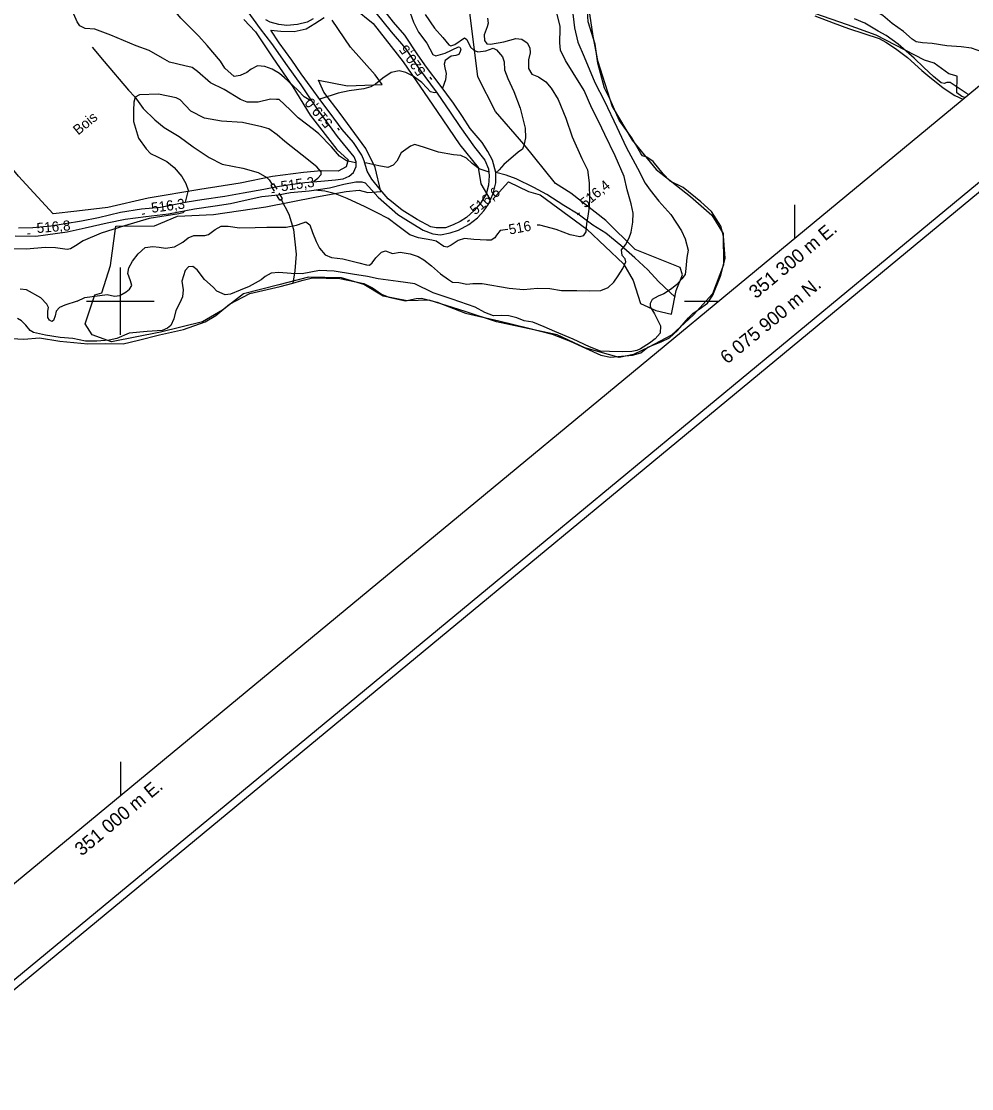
# Model space of a CAD drawing. Extents: x 347059 to 352153, y 6073752 to 6078601.
# Drawn here: x 350955.9 to 351378.9, y 6075549.6 to 6076024.5 of the extents above; entities that cross this region are included whole.
import ezdxf

# ---------------------------------------------------------------- set-up
doc = ezdxf.new("R2010")
doc.units = 0
for name, color, linetype in [('Level 1', 7, 'Continuous'), ('Level 2', 7, 'Continuous'), ('Level 21', 7, 'Continuous'), ('Level 22', 7, 'Continuous'), ('Level 26', 7, 'Continuous'), ('Level 3', 7, 'Continuous'), ('Level 4', 7, 'Continuous'), ('Level 44', 7, 'Continuous'), ('Level 60', 7, 'Continuous'), ('Level 61', 7, 'Continuous')]:
    doc.layers.add(name, color=color, linetype=linetype)

msp = doc.modelspace()

# ---------------------------------------------------------------- linework, layer by layer
at = {"layer": 'Level 1'}
for points in [[(351067.54, 6076003.28), (351064.33, 6076004.41), (351061, 6076004.75), (351058.26, 6076003.32), (351056.28, 6076001.76), (351053.33, 6076000.43), (351050.66, 6076000), (351046.49, 6076003.64), (351044.51, 6076006.88), (351038.58, 6076013.82), (351034.94, 6076017.92), (351026.87, 6076025.96), (351023.59, 6076029.96), (351021.08, 6076033.82), (351018.95, 6076038.01), (351015.73, 6076043.8), (351011.84, 6076051.29), (351006.56, 6076061.33)], [(351128.99, 6076028.34), (351130.47, 6076024.14), (351132.72, 6076019.66), (351136.44, 6076014.85), (351139.14, 6076009.83), (351140.38, 6076009.16), (351144.53, 6076010.32), (351150.45, 6076013.25), (351151.06, 6076013.01), (351151.5, 6076012.18), (351151.28, 6076011.06), (351150.62, 6076009.82), (351149.37, 6076009.28), (351147.21, 6076009.03), (351144.58, 6076007.17), (351144.1, 6076005.41), (351144.35, 6076003.89), (351144.95, 6076001.34), (351144.68, 6075998.57)], [(351085.36, 6075988.98), (351083.98, 6075989.61), (351081.87, 6075991.01), (351079, 6075993.89), (351074.52, 6075998.05), (351073.05, 6075999.47), (351070.82, 6076001.3), (351067.54, 6076003.28)], [(351140.77, 6075992.82), (351139.78, 6075992.74), (351138.03, 6075993.24), (351136.37, 6075994.88), (351134.18, 6075997.27), (351130.32, 6076000.1), (351127.09, 6076001.72), (351124.07, 6076002.47), (351120.53, 6076001.83), (351116.85, 6075999.19), (351113.59, 6075996.52), (351111.44, 6075995.33), (351108.39, 6075994.58), (351101.9, 6075993.67), (351096.9, 6075992.58), (351089.23, 6075989.99), (351088.78, 6075989.8)], [(351144.68, 6075998.57), (351143.45, 6075994.86), (351143.3, 6075994.74)]]:
    msp.add_lwpolyline(points, dxfattribs=at)
at = {"layer": 'Level 2'}
for points in [[(351394.98, 6076006.41), (351394.56, 6076006.7), (351390.72, 6076008.51), (351386.33, 6076009.86), (351378.78, 6076012.53), (351374.27, 6076013.23), (351367.78, 6076013.57), (351361.34, 6076014.63), (351356.95, 6076015.03), (351354.16, 6076015.46), (351352.36, 6076016.61), (351348.57, 6076020.09), (351343.46, 6076023.52), (351339.31, 6076027.1), (351335.85, 6076029.25), (351330.86, 6076030.35), (351328.52, 6076032.12), (351326.69, 6076033.78), (351321.7, 6076038.81), (351319, 6076040.54), (351315.61, 6076041.66), (351309.69, 6076044)], [(351061.31, 6075988.58), (351056.44, 6075988.55), (351053.45, 6075989.72), (351046.26, 6075994.26), (351040.17, 6075997.2), (351034.38, 6076002.27), (351032, 6076003.97), (351028.75, 6076004.67), (351021.93, 6076006.44), (351018.76, 6076008.14), (351012.78, 6076011.57), (351007.05, 6076013.62), (350995.79, 6076018.42), (350988.6, 6076021.09), (350984.39, 6076021.36), (350981.9, 6076022.57), (350980.74, 6076024.39), (350979.26, 6076027.68)], [(351201.14, 6076030.4), (351202.11, 6076021.65), (351203.59, 6076015.27), (351206.5, 6076008.77), (351211.12, 6075997.31), (351215.55, 6075989.03), (351220.95, 6075977.43), (351225.12, 6075968.52), (351230.18, 6075959.18), (351233.58, 6075952.57), (351235.79, 6075949.37), (351239.74, 6075944.58), (351245.04, 6075938.54), (351249.75, 6075931.31), (351251.36, 6075927.73), (351252.73, 6075922.72), (351252.14, 6075919.52), (351251.72, 6075914.59), (351251.32, 6075911.95), (351249.97, 6075909.97), (351247.72, 6075907.49), (351245.28, 6075905.53), (351241.89, 6075903.28), (351239.33, 6075902.26), (351236.65, 6075900.74), (351235.88, 6075899), (351235.85, 6075897.49), (351237.78, 6075894.45), (351240.48, 6075889.12), (351240.25, 6075885.82), (351237.99, 6075883.19), (351235.57, 6075881.37), (351231.52, 6075878.81), (351229.82, 6075878.01), (351227.72, 6075877.67), (351223.34, 6075877.52), (351217.69, 6075877.61), (351213.77, 6075877.85), (351208.88, 6075879.68), (351201.6, 6075883.08), (351193.32, 6075886.55), (351188.66, 6075888.59), (351183.65, 6075890.72), (351179.68, 6075891.33), (351176.54, 6075892.66), (351172.94, 6075893.45), (351169.59, 6075893.65), (351166.13, 6075893.49), (351162.22, 6075894.96), (351157.94, 6075897.32), (351147.72, 6075900.89), (351139.23, 6075903.66), (351131.12, 6075907.7), (351126.86, 6075908.33), (351123.66, 6075908.81), (351114.77, 6075910.03)], [(351135.72, 6076027.57), (351139.79, 6076021.57), (351143.56, 6076017.32), (351146.25, 6076014.02), (351147.14, 6076013.58), (351148.91, 6076014.3), (351153.23, 6076017.23), (351154.27, 6076016.51), (351155.81, 6076013.02), (351157.35, 6076011.67), (351159.09, 6076011.03), (351162.61, 6076011.39), (351165.98, 6076012.54), (351167.43, 6076011.92), (351170.05, 6076008.7), (351170.89, 6076006.48), (351171, 6076002.96), (351172.51, 6075999.18), (351175.16, 6075993.3)], [(351163.35, 6076026.01), (351163.69, 6076023.75), (351163.29, 6076022.07), (351161.9, 6076018.59), (351162.14, 6076015.99), (351163.11, 6076014.54), (351164.81, 6076014.4), (351170.74, 6076015.35), (351175.99, 6076016.93), (351178.68, 6076016.57), (351181.07, 6076015.01), (351182.2, 6076012.76), (351182.39, 6076010.52), (351181.67, 6076007.35)], [(351196.36, 6075904.83), (351203.22, 6075904.71), (351208.86, 6075904.61), (351213.81, 6075904.72), (351217.12, 6075906.11), (351219.58, 6075908.5), (351221.64, 6075911.36), (351223.72, 6075914.5), (351225, 6075917.49), (351224.67, 6075918.81), (351223.41, 6075920.28), (351223.02, 6075922.88), (351224.89, 6075925.11), (351226.47, 6075928.17), (351227.3, 6075930.76), (351228.12, 6075935.23), (351228.18, 6075939.18), (351227.4, 6075943.34), (351225.63, 6075949.59), (351224.26, 6075955.53), (351220.19, 6075964.63), (351215.64, 6075974.13), (351212.98, 6075979.89), (351209.91, 6075985.96), (351206.39, 6075993.79), (351201.51, 6076001.67), (351198.11, 6076007.05), (351195.94, 6076011.75), (351195.59, 6076014.94), (351195.69, 6076021.33), (351195.77, 6076022.31), (351194.34, 6076028.31)], [(351367.81, 6075997.28), (351366.63, 6075996.94), (351365.27, 6075997.25), (351361.99, 6075999.97), (351357.58, 6076004.01), (351353.24, 6076008.12), (351346.16, 6076014.32), (351340.79, 6076018.22), (351337.23, 6076020.16), (351331.33, 6076023.73), (351326.83, 6076025.67)], [(351181.67, 6076007.35), (351181.69, 6076003.62), (351183.14, 6076000.99), (351186.13, 6075999.81), (351189.33, 6075997.61), (351191.7, 6075994.83), (351194.92, 6075989.83), (351198.25, 6075981.45), (351201.09, 6075973.18), (351205.34, 6075963.57), (351207.9, 6075958.41), (351208.7, 6075952.67), (351208.87, 6075944.9), (351208.44, 6075940.91), (351208.04, 6075937.86), (351207.43, 6075934.54), (351207.23, 6075930.88), (351205.96, 6075929.12), (351204.58, 6075928.72), (351200.28, 6075929.57), (351194.02, 6075931.95), (351186.73, 6075933.83), (351185.55, 6075933.82)], [(351377.49, 6075991.96), (351376.39, 6075992.64), (351369.27, 6075997.32), (351367.81, 6075997.28)], [(351175.16, 6075993.3), (351177.99, 6075985.97), (351180.21, 6075977.04), (351180.26, 6075972.67), (351179.59, 6075969.28), (351178.98, 6075967.68), (351177.03, 6075966.4), (351170.65, 6075960.85), (351168.62, 6075958.5), (351167.13, 6075957.18)], [(351085.98, 6075953.1), (351086.19, 6075953.39), (351087.93, 6075954.76), (351089.34, 6075956.37), (351089.42, 6075957.52), (351087.44, 6075959.83), (351080.86, 6075965.04), (351073.2, 6075971.06), (351069.83, 6075974.07), (351066.09, 6075976.74), (351062.93, 6075977.65), (351054.39, 6075979.56), (351044.97, 6075980.19), (351037.39, 6075981.45), (351031.44, 6075984.52), (351026.57, 6075989.6), (351024.85, 6075990.53), (351017, 6075992.1), (351008.51, 6075991.79), (351006.56, 6075990.76), (351006.05, 6075988.6), (351005.85, 6075984.8), (351005.92, 6075979.9), (351008.11, 6075972.52), (351011.43, 6075967.86), (351013.43, 6075965.68), (351016.49, 6075964.28), (351020.64, 6075962.22), (351023.97, 6075959.57), (351027.33, 6075955.49), (351029.19, 6075952.38), (351030.19, 6075949.35), (351028.83, 6075944.02)], [(351104.96, 6075961.63), (351104.08, 6075961.66), (351100.7, 6075962.48), (351097.56, 6075964.6), (351094, 6075968.76), (351088.33, 6075974.46), (351085.97, 6075976.45), (351079.19, 6075981.6), (351075.51, 6075985.13), (351070.62, 6075989.76), (351069.55, 6075989.78), (351066.77, 6075989.93), (351061.31, 6075988.58)], [(351164, 6075957.53), (351163.66, 6075957.61), (351159.66, 6075958.92), (351156.55, 6075961.32), (351154, 6075963.68), (351151.58, 6075964.81), (351148.32, 6075965.07), (351141.56, 6075966.34), (351135.34, 6075968.35), (351131.01, 6075969.71), (351129.11, 6075969), (351124.96, 6075965.96), (351122.99, 6075962.39), (351121.36, 6075960.59), (351118.99, 6075959.48), (351115.12, 6075960.3), (351109.77, 6075961.48), (351108.79, 6075961.51)], [(351123.57, 6075933.54), (351119.15, 6075936.84), (351114.04, 6075939.41), (351109, 6075942.05), (351100.89, 6075945.65), (351095.74, 6075947.8), (351090.95, 6075948.9), (351086.41, 6075949.38), (351086.38, 6075949.48)], [(351028.57, 6075940.24), (351028.56, 6075940.13), (351027.82, 6075939.39), (351026.06, 6075938.95), (351012.77, 6075936.78), (351001.83, 6075933.56), (350991.39, 6075930.22), (350983.46, 6075926.89), (350980, 6075924.72), (350977.88, 6075923.3), (350976.28, 6075923), (350971.09, 6075923.78), (350966.64, 6075923.85), (350958.1, 6075923.09), (350952.14, 6075923.35)], [(350980.85, 6075900.05), (350984.22, 6075901.73), (350994.09, 6075902.96), (350997.42, 6075902.19), (350999.75, 6075902.58), (351002.53, 6075904.16), (351004.13, 6075905.4), (351005.04, 6075906.99), (351004.54, 6075909.12), (351003.27, 6075912.33), (351003.81, 6075914.81), (351005.39, 6075917.79), (351008, 6075921.12), (351011.01, 6075923.84), (351014.42, 6075924.35), (351017.27, 6075923.98), (351020.06, 6075923.68), (351024.12, 6075924.22), (351027.86, 6075926.23), (351030.16, 6075928.21), (351032.75, 6075929.23), (351037.64, 6075929.27), (351039.25, 6075929.72), (351042.14, 6075931.94), (351044.91, 6075933.37), (351047.93, 6075933.42), (351053.05, 6075932.72), (351060.02, 6075932.8), (351065.2, 6075932.96), (351073.82, 6075932.99), (351078.33, 6075933.78), (351081.42, 6075934.83), (351082.56, 6075935.29), (351084.37, 6075934.01), (351085.49, 6075930.53), (351087.14, 6075926.58), (351088.65, 6075923.58), (351091.16, 6075920.63), (351093.94, 6075919.4), (351099, 6075918.92), (351106.12, 6075917.12), (351109.57, 6075916.2), (351110.85, 6075916.1), (351112.06, 6075917.01), (351113.66, 6075919.33), (351116.2, 6075921.79), (351118.04, 6075922.43), (351121.11, 6075921.18), (351124.59, 6075921.76), (351128.99, 6075921.12), (351132.56, 6075919.9), (351135.11, 6075918.47), (351138.43, 6075915.82), (351142.47, 6075912.18), (351146.09, 6075909.66), (351147.79, 6075908.44), (351150.65, 6075908.36), (351154.18, 6075907.64), (351156.92, 6075907.85), (351161, 6075907.88), (351173.02, 6075905.77), (351179.43, 6075905.25), (351185.62, 6075905.76), (351191.13, 6075905.68), (351196.36, 6075904.83)], [(351172.4, 6075931.91), (351168.99, 6075931.52), (351167.4, 6075929.35), (351166.68, 6075928.19), (351165.03, 6075927.17), (351162.95, 6075927.12), (351157.4, 6075927.43), (351153.14, 6075927.91), (351150.36, 6075926.99), (351147.29, 6075925.01), (351145.43, 6075924.08), (351144.02, 6075924.34), (351140.54, 6075926.7), (351138.65, 6075927.21), (351132.71, 6075928.27), (351128.8, 6075929.59), (351123.57, 6075933.54)], [(351114.77, 6075910.03), (351109.96, 6075910.99), (351103.35, 6075912.03), (351095.18, 6075913.33), (351088.67, 6075913.64), (351080.87, 6075912.17), (351075.97, 6075912.28), (351070.49, 6075912.79), (351067.16, 6075912.48), (351064.46, 6075910.96), (351062.7, 6075909.59), (351057.38, 6075906.62), (351053.3, 6075904.85), (351049, 6075903.17), (351046.61, 6075902.86), (351042.98, 6075904.45), (351041.31, 6075906.25), (351037.39, 6075909.74), (351034.23, 6075913.9), (351032.19, 6075915.51), (351030.37, 6075915.29), (351028.82, 6075913.68), (351027.32, 6075908.89), (351027.97, 6075905), (351027.61, 6075901.99), (351026.55, 6075899.33), (351024.72, 6075895.86), (351023.87, 6075892.17), (351022.51, 6075889.24), (351020.98, 6075888.06), (351018.6, 6075886.95), (351012.01, 6075886.54), (351003.88, 6075885.74), (350998.38, 6075883.43), (350995.01, 6075882.69)], [(350980.85, 6075900.05), (350975.32, 6075898.25), (350972.95, 6075897.28), (350971.46, 6075895.6), (350971.01, 6075893.46), (350970.28, 6075891.35), (350969.54, 6075890.98), (350968.42, 6075891.5), (350967.72, 6075892.79), (350967.78, 6075895.53), (350968.05, 6075897.24), (350967.3, 6075898.75), (350964.54, 6075901.5), (350958.18, 6075905.04), (350955.39, 6075905.34)], [(350995.01, 6075882.69), (350989.57, 6075882.18), (350984.45, 6075882.23), (350978.92, 6075883.4), (350973.26, 6075883.92), (350966.69, 6075884.88), (350961.29, 6075886.03), (350959.84, 6075886.94), (350957.92, 6075889.34), (350955.98, 6075891.31), (350954.17, 6075892.32)]]:
    msp.add_lwpolyline(points, dxfattribs=at)
at = {"layer": 'Level 21'}
for points in [[(351123.45, 6075938.63), (351128.32, 6075935.62), (351134.76, 6075931.68), (351139.06, 6075929.98), (351142.52, 6075929.59), (351146.86, 6075930.45), (351150.47, 6075931.59), (351155.09, 6075934.09), (351159, 6075937.12), (351161.74, 6075940.21), (351163.86, 6075943.23), (351165.97, 6075947.88), (351167.05, 6075952.63), (351167.14, 6075957.31), (351165.64, 6075962.83), (351163.62, 6075966.64), (351161.04, 6075970.58), (351155.7, 6075976.9), (351152.35, 6075982.13), (351148.31, 6075988.13), (351142.28, 6075996.1), (351136.21, 6076004.19), (351132.45, 6076009.67), (351126.57, 6076018.44), (351121.6, 6076024.11), (351115.66, 6076031.78)], [(350954.73, 6075932.59), (350961.02, 6075932.83), (350969.1, 6075933.51), (350975.5, 6075934.52), (350982.74, 6075935.77), (350990.24, 6075937.24), (351000.02, 6075939.57), (351009.45, 6075941.07), (351017.86, 6075941.8), (351029.68, 6075944.19), (351036.33, 6075945.25), (351046.48, 6075946.68), (351054.69, 6075948.3), (351063.8, 6075949.83), (351069.9, 6075951.11), (351074.57, 6075951.78), (351082.15, 6075952.8), (351089.28, 6075953.37), (351095.77, 6075953.99), (351099.1, 6075954.46), (351101.89, 6075955.59), (351103.76, 6075957.29), (351104.96, 6075960), (351104.95, 6075962.08), (351104.11, 6075964.27), (351096.66, 6075973.31), (351091.85, 6075979.87), (351087.69, 6075985.47), (351083.15, 6075992.32), (351080.41, 6075996.28), (351074.37, 6076004.78), (351067.41, 6076014.66), (351062.44, 6076021.15), (351056.14, 6076029.88)], [(351085.79, 6076025.7), (351083.09, 6076024.2), (351078.85, 6076023.13), (351074.07, 6076022.72), (351070.54, 6076023.12), (351066.71, 6076024.17), (351064.74, 6076025.21)], [(351113.75, 6076028.34), (351120.52, 6076019.93), (351126.92, 6076012.41), (351132.59, 6076003.99), (351140.97, 6075992.54), (351146.85, 6075984.14), (351151.05, 6075977.76), (351157.63, 6075968.6), (351162.21, 6075962.76), (351163.87, 6075958.94), (351164.17, 6075955.78), (351163.8, 6075951.61), (351162.85, 6075947.63), (351160.31, 6075943.66), (351157.42, 6075940.3), (351154.04, 6075937.27), (351151.31, 6075935.52), (351148.08, 6075933.95), (351144.65, 6075932.59), (351140.56, 6075932.68), (351138.16, 6075933.06), (351132.07, 6075936.39), (351125.44, 6075940.55), (351119.26, 6075945.52), (351115.65, 6075949.72), (351111.99, 6075954.34), (351109.81, 6075957.8), (351108.55, 6075962.4), (351107.54, 6075964.98), (351103.75, 6075970.66), (351098.69, 6075976.34), (351093.39, 6075983.68), (351089.29, 6075989.1), (351084.88, 6075995.09), (351080.44, 6076001.2), (351076.28, 6076007.24), (351070.66, 6076015.05), (351066.98, 6076020.6), (351071.48, 6076020.19), (351077.3, 6076020.06), (351082.68, 6076021.19), (351086.63, 6076023.51), (351090.66, 6076026.19)], [(350953.23, 6075929.14), (350962.36, 6075928.94), (350966.76, 6075929.47), (350976.33, 6075930.88), (350984.4, 6075932.66), (350994.17, 6075934.91), (351002.18, 6075936.58), (351011.4, 6075937.69), (351021.41, 6075938.94), (351033, 6075941.05), (351042.21, 6075942.45), (351049.03, 6075943.5), (351055.52, 6075944.95), (351062.99, 6075946.55), (351070.19, 6075947.31), (351075.74, 6075948.36), (351084.04, 6075949.14), (351093.03, 6075950.44), (351099.52, 6075952.04), (351104.75, 6075953.19), (351107.47, 6075953.15), (351109.01, 6075952.72), (351114.81, 6075946.32), (351123.45, 6075938.63)]]:
    msp.add_lwpolyline(points, dxfattribs=at)
at = {"layer": 'Level 22'}
msp.add_lwpolyline([(351246.87, 6075901.79), (351239.58, 6075908.84), (351234.72, 6075914.02), (351229.06, 6075919.28), (351222.81, 6075924.79), (351216.11, 6075930.22), (351210.34, 6075933.9), (351203.79, 6075938.78), (351197.42, 6075942.54), (351189.83, 6075947.44), (351184.08, 6075950.54), (351176.14, 6075954.4), (351171.69, 6075956.12), (351167.14, 6075957.31)], dxfattribs=at)
at = {"layer": 'Level 26'}
for p, q in [((351068.19, 6075952.27), (351066.95, 6075951.49)), ((351066.95, 6075951.49), (351068.48, 6075949.04)), ((351068.19, 6075952.27), (351069.71, 6075949.81)), ((351070.94, 6075944.91), (351069.49, 6075947.39)), ((351072.2, 6075945.66), (351070.71, 6075948.13)), ((351070.94, 6075944.91), (351072.2, 6075945.66))]:
    msp.add_line(p, q, dxfattribs=at)
at = {"layer": 'Level 3'}
for p, q in [((351138.58, 6075998.72), (351137.89, 6075999.7)), ((351097.57, 6075976.09), (351096.8, 6075977.01)), ((351067.42, 6075948.37), (351068.61, 6075948.53)), ((351009.73, 6075938.81), (351010.92, 6075938.97)), ((351154.53, 6075935.44), (351155.45, 6075936.21)), ((351203.47, 6075938.5), (351204.39, 6075939.27)), ((350958.64, 6075930), (350959.84, 6075930.1))]:
    msp.add_line(p, q, dxfattribs=at)
at = {"layer": 'Level 4'}
for points in [[(351268.38, 6075929.02), (351267.23, 6075933.43), (351263.11, 6075939.98), (351258.39, 6075944.18), (351250.51, 6075950.6), (351244.76, 6075953.42), (351241.66, 6075956.73), (351237.19, 6075962.18), (351234.28, 6075964.17), (351232.46, 6075964.67), (351231.67, 6075965.8), (351227.62, 6075972.73), (351222.07, 6075980.5), (351218.08, 6075989.72), (351215.52, 6075994.83), (351212.56, 6076005.89), (351211.39, 6076014.33), (351208.24, 6076024.26), (351207.59, 6076033.88)], [(351309.11, 6076027.06), (351317.23, 6076023.89), (351324.03, 6076021.33), (351337.77, 6076016.94), (351340.66, 6076015.32), (351345.06, 6076012.41), (351350.32, 6076008.44), (351356.66, 6076002.61), (351359.42, 6076000.43), (351366.2, 6075994.97), (351371.48, 6075991.61), (351374.96, 6075989.87)], [(350987.4, 6076013.03), (350992.75, 6076006.73), (351003.59, 6075993.96), (351006.39, 6075990.92), (351010.21, 6075985.74), (351015.31, 6075980.65), (351019.43, 6075977.29), (351026.13, 6075973.24), (351032.38, 6075968.66), (351039.46, 6075963.88), (351045.37, 6075960.96), (351054.56, 6075959.14), (351061.3, 6075957.21), (351065.17, 6075955.06), (351066.17, 6075954.02), (351067.55, 6075951.89)], [(351071.6, 6075945.27), (351074.96, 6075938.76), (351077.08, 6075931.94), (351078.3, 6075920.96), (351077.7, 6075913.45), (351076.78, 6075908.07)], [(350949.09, 6075883.62), (350957.08, 6075883.1), (350964.04, 6075883.65), (350973.05, 6075882.17), (350985.6, 6075881.02), (350993.44, 6075881.13), (351001.24, 6075881.11), (351008.09, 6075882.69), (351017.45, 6075885.03), (351028.05, 6075887.49), (351037.73, 6075890.9), (351042.44, 6075893.7), (351048.51, 6075898.67), (351057.66, 6075903.44), (351071.18, 6075906.54), (351076.78, 6075908.07), (351080.81, 6075909.17), (351085.46, 6075910.42), (351097.72, 6075910.16), (351108.43, 6075907.87), (351112.21, 6075906.01), (351116.17, 6075903.19), (351119.43, 6075901.87), (351126.98, 6075900.24), (351131.68, 6075901.16), (351134.1, 6075901.3), (351141.03, 6075899.61), (351153.64, 6075894.73), (351168.49, 6075891.2), (351181.79, 6075888.02), (351192.19, 6075885.27), (351200.16, 6075882.21), (351213.89, 6075876.06), (351218.15, 6075875.05), (351228.02, 6075876.03), (351231.61, 6075877.01), (351234.71, 6075879.5), (351240.69, 6075881.94), (351244.44, 6075883.64), (351247.99, 6075887.03), (351252.89, 6075892.59), (351255.01, 6075894.64), (351257.55, 6075896.45), (351261.28, 6075899.17), (351263.74, 6075902.63), (351267.1, 6075911.15), (351269.23, 6075919.09), (351268.38, 6075929.02)]]:
    msp.add_lwpolyline(points, dxfattribs=at)
at = {"layer": 'Level 44'}
for points in [[(351165.95, 6075945.62), (351172.76, 6075953.06), (351181.59, 6075948.83), (351186.8, 6075947.37), (351207.61, 6075932.01), (351223.87, 6075916.58), (351228.27, 6075909.24), (351231.48, 6075899), (351238.33, 6075895.93), (351245.24, 6075894.23), (351247.42, 6075904.81), (351250.22, 6075911.74), (351249.16, 6075915.02), (351229.14, 6075923.06), (351216.02, 6075935.93), (351200.51, 6075948.11), (351193.62, 6075952.32), (351179.61, 6075969.91), (351166.99, 6075984.35), (351159.1, 6075999.9), (351154.49, 6076036.97)], [(351207.89, 6076033.86), (351210.33, 6076017.96), (351212.37, 6076007.12), (351218.92, 6075986.6), (351227.79, 6075971.61), (351238.49, 6075958.59), (351253.76, 6075946.55), (351263.21, 6075938.32), (351268.26, 6075930.16), (351268.51, 6075916.25), (351263.49, 6075903.31), (351255.08, 6075893.95), (351245.33, 6075884.96), (351235.19, 6075879.52), (351228.36, 6075876.23), (351221.96, 6075874.93), (351206.67, 6075879.19), (351194.39, 6075885.05), (351167.42, 6075890.79), (351153.54, 6075895.49), (351137.4, 6075900.4), (351127.68, 6075900.23), (351116.95, 6075902.19), (351108.41, 6075907.47), (351098.42, 6075910.35), (351083.69, 6075910.64), (351070.48, 6075907.27), (351054.85, 6075903.22), (351045.52, 6075896.07), (351036.62, 6075890.76), (351017.93, 6075886.26), (350996.08, 6075881.96), (350987.41, 6075885.04), (350984.37, 6075889.97), (350988.68, 6075902.79), (350991.7, 6075903.66), (350995.63, 6075915.86), (350997.94, 6075933.41), (351015.27, 6075933.53), (351025.37, 6075937.91), (351041.46, 6075938.66), (351064.69, 6075941.98), (351087.26, 6075946.49), (351100.52, 6075948.8), (351106.32, 6075949.48), (351110.2, 6075948.39), (351115.87, 6075948.77), (351113.4, 6075959.44), (351109.2, 6075967.92), (351097.79, 6075983.53), (351090.51, 6075993.02), (351088.15, 6075998.36), (351101.04, 6075995.81), (351116.58, 6075996.41), (351113.44, 6076000.77), (351102.46, 6076013.02), (351094.28, 6076025.11)], [(351104.02, 6076030.42), (351112.51, 6076023.63), (351125.86, 6076006.52), (351141.02, 6075984.35), (351151.13, 6075969.57), (351159.24, 6075959.45), (351160.43, 6075952.28), (351164.44, 6075945.43)], [(351375.86, 6075990.61), (351374.58, 6075991.06), (351372.31, 6075992.75), (351372.4, 6076000.1), (351368.68, 6076001.18), (351362.25, 6076005.95), (351357.91, 6076007.26), (351336.39, 6076018.43), (351323.66, 6076023.05), (351309.08, 6076028.09)], [(351054.97, 6076025.37), (351060.19, 6076019.82), (351067.87, 6076008.29), (351076.72, 6075995.36), (351084.45, 6075982.82), (351096.38, 6075967.44), (351101.42, 6075962.93), (351100.55, 6075959.85), (351096.91, 6075957.89), (351089.41, 6075957.98), (351081.51, 6075957.21), (351067.7, 6075955.49), (351053.27, 6075952.57), (351035.31, 6075949.73), (351012.45, 6075945.84), (350994.37, 6075941.74), (350980.56, 6075940.02), (350970.16, 6075938.87), (350954.6, 6075955.7), (350949.47, 6075962.05)]]:
    msp.add_lwpolyline(points, dxfattribs=at)
at = {"layer": 'Level 60'}
for p, q in [((351300, 6075942.93), (351300, 6075927.93)), ((351251.13, 6075900), (351266.2, 6075900)), ((351000, 6075695.03), (351000, 6075680.03))]:
    msp.add_line(p, q, dxfattribs=at)
msp.add_lwpolyline([(347109.95, 6075761.81), (348728.53, 6073803.05), (351407.22, 6076016.53), (349788.63, 6077975.29)], close=True, dxfattribs=at)
for points in [[(348724.12, 6073756.59), (352148.69, 6076586.41)], [(348723.67, 6073751.88), (352153.39, 6076585.96)]]:
    msp.add_lwpolyline(points, dxfattribs=at)
at = {"layer": 'Level 61'}
for p, q in [((351000, 6075885), (351000, 6075915)), ((350985, 6075900), (351015, 6075900))]:
    msp.add_line(p, q, dxfattribs=at)

# ---------------------------------------------------------------- texts
at = {"layer": 'Level 2'}
msp.add_text('516', height=4.5, rotation=10.644, dxfattribs=at).set_placement((351173.28, 6075929.64))
at = {"layer": 'Level 3'}
for s, rotation, p in [('520,5', 125.2485, (351136.13, 6076002.28)), ('519,0', 130.0726, (351094.82, 6075979.44)), ('515,3', 7.8374, (351071.71, 6075948.9)), ('516,6', 39.62, (351157.89, 6075938.16)), ('516,4', 39.62, (351206.83, 6075941.22)), ('516,3', 7.4346, (351014.02, 6075939.32)), ('516,8', 4.7753, (350962.94, 6075930.3))]:
    msp.add_text(s, height=4.5, rotation=rotation, dxfattribs=at).set_placement(p)
at = {"layer": 'Level 44'}
msp.add_text('Bois', height=4.5, rotation=39.568, dxfattribs=at).set_placement((350981.25, 6075973.71))
at = {"layer": 'Level 61'}
for s, height, rotation, p in [('351 300 m E. ', 6, 39.813, (351282.88, 6075900.83)), ('6 075 900 m N.', 6.0001, 39.3644, (351270.07, 6075871.77)), ('351 000 m E. ', 6, 39.813, (350982.79, 6075652.85))]:
    msp.add_text(s, height=height, rotation=rotation, dxfattribs=at).set_placement(p)

doc.saveas('drawing.dxf')
